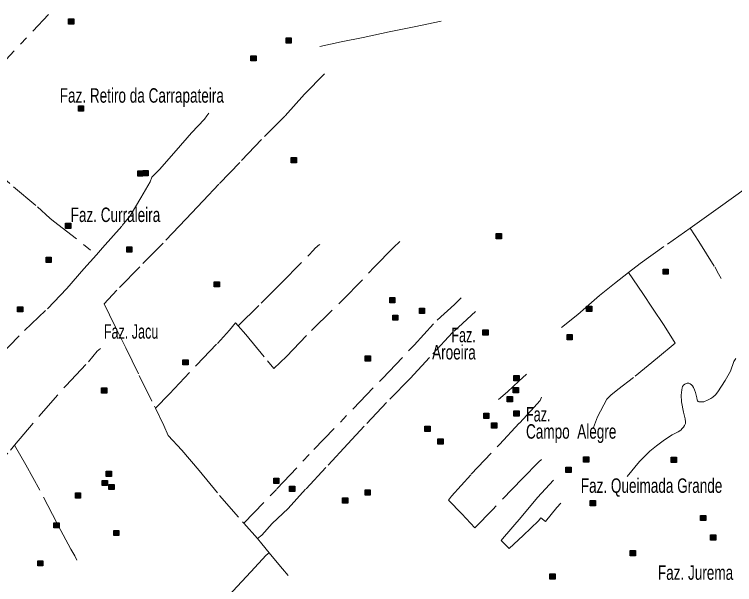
# Model space of a CAD drawing. Extents: x 445.6 to 500, y 8618.1 to 8673.4.
# Drawn here: x 465.21 to 473.17, y 8667.1 to 8673.41 of the extents above; entities that cross this region are included whole.
import ezdxf
from ezdxf.enums import TextEntityAlignment as Align

# ---------------------------------------------------------------- set-up
doc = ezdxf.new("R2010")
doc.units = 0
doc.header["$LTSCALE"] = 0.064
doc.linetypes.add('DOT_DASHED', pattern=[7.7, 5, -1.2, 0.3, -1.2])
doc.layers.add('2', color=7, linetype='Continuous', lineweight=25)
doc.layers.add('22', color=7, linetype='DOT_DASHED', lineweight=13)
doc.layers.add('61', color=7, linetype='Continuous')

msp = doc.modelspace()

# ---------------------------------------------------------------- hatches: boundary and pattern name
at = {"layer": '2'}
for points in [[(465.8078, 8673.3606), (465.8658, 8673.3606), (465.8658, 8673.3026), (465.8078, 8673.3026)], [(468.2112, 8673.1506), (468.2692, 8673.1506), (468.2692, 8673.0926), (468.2112, 8673.0926)], [(467.8227, 8672.9541), (467.8807, 8672.9541), (467.8807, 8672.8961), (467.8227, 8672.8961)], [(465.9159, 8672.3984), (465.9739, 8672.3984), (465.9739, 8672.3404), (465.9159, 8672.3404)], [(468.2684, 8671.8287), (468.3264, 8671.8287), (468.3264, 8671.7707), (468.2684, 8671.7707)], [(466.5717, 8671.6798), (466.6297, 8671.6798), (466.6297, 8671.6218), (466.5717, 8671.6218)], [(466.6291, 8671.6832), (466.6871, 8671.6832), (466.6871, 8671.6252), (466.6291, 8671.6252)], [(465.7746, 8671.1004), (465.8326, 8671.1004), (465.8326, 8671.0424), (465.7746, 8671.0424)], [(470.5333, 8670.9885), (470.5913, 8670.9885), (470.5913, 8670.9305), (470.5333, 8670.9305)], [(466.4499, 8670.841), (466.5079, 8670.841), (466.5079, 8670.783), (466.4499, 8670.783)], [(465.5581, 8670.7258), (465.6161, 8670.7258), (465.6161, 8670.6678), (465.5581, 8670.6678)], [(472.3785, 8670.5952), (472.4365, 8670.5952), (472.4365, 8670.5372), (472.3785, 8670.5372)], [(467.4159, 8670.4548), (467.4739, 8670.4548), (467.4739, 8670.3968), (467.4159, 8670.3968)], [(469.3571, 8670.2791), (469.4151, 8670.2791), (469.4151, 8670.2211), (469.3571, 8670.2211)], [(465.2441, 8670.178), (465.3021, 8670.178), (465.3021, 8670.12), (465.2441, 8670.12)], [(469.6848, 8670.1605), (469.7428, 8670.1605), (469.7428, 8670.1025), (469.6848, 8670.1025)], [(471.5339, 8670.1847), (471.5919, 8670.1847), (471.5919, 8670.1267), (471.5339, 8670.1267)], [(469.3909, 8670.0859), (469.4489, 8670.0859), (469.4489, 8670.0279), (469.3909, 8670.0279)], [(470.3868, 8669.9209), (470.4448, 8669.9209), (470.4448, 8669.8629), (470.3868, 8669.8629)], [(471.3177, 8669.8699), (471.3757, 8669.8699), (471.3757, 8669.8119), (471.3177, 8669.8119)], [(467.0698, 8669.5923), (467.1278, 8669.5923), (467.1278, 8669.5343), (467.0698, 8669.5343)], [(469.0869, 8669.6353), (469.1449, 8669.6353), (469.1449, 8669.5773), (469.0869, 8669.5773)], [(470.73, 8669.4159), (470.788, 8669.4159), (470.788, 8669.3579), (470.73, 8669.3579)], [(466.1713, 8669.2806), (466.2293, 8669.2806), (466.2293, 8669.2226), (466.1713, 8669.2226)], [(470.7232, 8669.2838), (470.7812, 8669.2838), (470.7812, 8669.2258), (470.7232, 8669.2258)], [(470.6564, 8669.1837), (470.7144, 8669.1837), (470.7144, 8669.1257), (470.6564, 8669.1257)], [(470.3963, 8669.0007), (470.4543, 8669.0007), (470.4543, 8668.9427), (470.3963, 8668.9427)], [(470.73, 8669.0263), (470.788, 8669.0263), (470.788, 8668.9683), (470.73, 8668.9683)], [(470.4841, 8668.8923), (470.5421, 8668.8923), (470.5421, 8668.8343), (470.4841, 8668.8343)], [(469.745, 8668.8576), (469.803, 8668.8576), (469.803, 8668.7996), (469.745, 8668.7996)], [(469.8896, 8668.7161), (469.9476, 8668.7161), (469.9476, 8668.6581), (469.8896, 8668.6581)], [(471.5001, 8668.5181), (471.5581, 8668.5181), (471.5581, 8668.4601), (471.5001, 8668.4601)], [(472.4696, 8668.5147), (472.5276, 8668.5147), (472.5276, 8668.4567), (472.4696, 8668.4567)], [(471.3042, 8668.4026), (471.3622, 8668.4026), (471.3622, 8668.3446), (471.3042, 8668.3446)], [(466.2236, 8668.3591), (466.2816, 8668.3591), (466.2816, 8668.3011), (466.2236, 8668.3011)], [(466.1797, 8668.2575), (466.2377, 8668.2575), (466.2377, 8668.1995), (466.1797, 8668.1995)], [(468.0745, 8668.2811), (468.1325, 8668.2811), (468.1325, 8668.2231), (468.0745, 8668.2231)], [(466.254, 8668.2134), (466.312, 8668.2134), (466.312, 8668.1554), (466.254, 8668.1554)], [(468.2491, 8668.1922), (468.3071, 8668.1922), (468.3071, 8668.1342), (468.2491, 8668.1342)], [(465.8823, 8668.1195), (465.9403, 8668.1195), (465.9403, 8668.0615), (465.8823, 8668.0615)], [(469.0845, 8668.1524), (469.1425, 8668.1524), (469.1425, 8668.0944), (469.0845, 8668.0944)], [(468.8355, 8668.0636), (468.8935, 8668.0636), (468.8935, 8668.0056), (468.8355, 8668.0056)], [(471.5727, 8668.0332), (471.6307, 8668.0332), (471.6307, 8667.9752), (471.5727, 8667.9752)], [(472.7935, 8667.8705), (472.8515, 8667.8705), (472.8515, 8667.8125), (472.7935, 8667.8125)], [(465.6439, 8667.7891), (465.7019, 8667.7891), (465.7019, 8667.7311), (465.6439, 8667.7311)], [(466.3059, 8667.7044), (466.3639, 8667.7044), (466.3639, 8667.6464), (466.3059, 8667.6464)], [(472.9049, 8667.6537), (472.9629, 8667.6537), (472.9629, 8667.5957), (472.9049, 8667.5957)], [(472.0152, 8667.4809), (472.0732, 8667.4809), (472.0732, 8667.4229), (472.0152, 8667.4229)], [(465.4658, 8667.369), (465.5238, 8667.369), (465.5238, 8667.311), (465.4658, 8667.311)], [(471.1269, 8667.2234), (471.1849, 8667.2234), (471.1849, 8667.1654), (471.1269, 8667.1654)]]:
    msp.add_hatch(color=256, dxfattribs=at).paths.add_polyline_path(points)

# ---------------------------------------------------------------- linework, layer by layer
for points in [[(465.8078, 8673.3606), (465.8658, 8673.3606), (465.8658, 8673.3026), (465.8078, 8673.3026)], [(468.2112, 8673.1506), (468.2692, 8673.1506), (468.2692, 8673.0926), (468.2112, 8673.0926)], [(467.8227, 8672.9541), (467.8807, 8672.9541), (467.8807, 8672.8961), (467.8227, 8672.8961)], [(465.9159, 8672.3984), (465.9739, 8672.3984), (465.9739, 8672.3404), (465.9159, 8672.3404)], [(468.2684, 8671.8287), (468.3264, 8671.8287), (468.3264, 8671.7707), (468.2684, 8671.7707)], [(466.5717, 8671.6798), (466.6297, 8671.6798), (466.6297, 8671.6218), (466.5717, 8671.6218)], [(466.6291, 8671.6832), (466.6871, 8671.6832), (466.6871, 8671.6252), (466.6291, 8671.6252)], [(465.7746, 8671.1004), (465.8326, 8671.1004), (465.8326, 8671.0424), (465.7746, 8671.0424)], [(470.5333, 8670.9885), (470.5913, 8670.9885), (470.5913, 8670.9305), (470.5333, 8670.9305)], [(466.4499, 8670.841), (466.5079, 8670.841), (466.5079, 8670.783), (466.4499, 8670.783)], [(465.5581, 8670.7258), (465.6161, 8670.7258), (465.6161, 8670.6678), (465.5581, 8670.6678)], [(472.3785, 8670.5952), (472.4365, 8670.5952), (472.4365, 8670.5372), (472.3785, 8670.5372)], [(467.4159, 8670.4548), (467.4739, 8670.4548), (467.4739, 8670.3968), (467.4159, 8670.3968)], [(469.3571, 8670.2791), (469.4151, 8670.2791), (469.4151, 8670.2211), (469.3571, 8670.2211)], [(465.2441, 8670.178), (465.3021, 8670.178), (465.3021, 8670.12), (465.2441, 8670.12)], [(469.6848, 8670.1605), (469.7428, 8670.1605), (469.7428, 8670.1025), (469.6848, 8670.1025)], [(471.5339, 8670.1847), (471.5919, 8670.1847), (471.5919, 8670.1267), (471.5339, 8670.1267)], [(469.3909, 8670.0859), (469.4489, 8670.0859), (469.4489, 8670.0279), (469.3909, 8670.0279)], [(470.3868, 8669.9209), (470.4448, 8669.9209), (470.4448, 8669.8629), (470.3868, 8669.8629)], [(471.3177, 8669.8699), (471.3757, 8669.8699), (471.3757, 8669.8119), (471.3177, 8669.8119)], [(467.0698, 8669.5923), (467.1278, 8669.5923), (467.1278, 8669.5343), (467.0698, 8669.5343)], [(469.0869, 8669.6353), (469.1449, 8669.6353), (469.1449, 8669.5773), (469.0869, 8669.5773)], [(470.73, 8669.4159), (470.788, 8669.4159), (470.788, 8669.3579), (470.73, 8669.3579)], [(466.1713, 8669.2806), (466.2293, 8669.2806), (466.2293, 8669.2226), (466.1713, 8669.2226)], [(470.7232, 8669.2838), (470.7812, 8669.2838), (470.7812, 8669.2258), (470.7232, 8669.2258)], [(470.6564, 8669.1837), (470.7144, 8669.1837), (470.7144, 8669.1257), (470.6564, 8669.1257)], [(470.3963, 8669.0007), (470.4543, 8669.0007), (470.4543, 8668.9427), (470.3963, 8668.9427)], [(470.73, 8669.0263), (470.788, 8669.0263), (470.788, 8668.9683), (470.73, 8668.9683)], [(470.4841, 8668.8923), (470.5421, 8668.8923), (470.5421, 8668.8343), (470.4841, 8668.8343)], [(469.745, 8668.8576), (469.803, 8668.8576), (469.803, 8668.7996), (469.745, 8668.7996)], [(469.8896, 8668.7161), (469.9476, 8668.7161), (469.9476, 8668.6581), (469.8896, 8668.6581)], [(471.5001, 8668.5181), (471.5581, 8668.5181), (471.5581, 8668.4601), (471.5001, 8668.4601)], [(472.4696, 8668.5147), (472.5276, 8668.5147), (472.5276, 8668.4567), (472.4696, 8668.4567)], [(471.3042, 8668.4026), (471.3622, 8668.4026), (471.3622, 8668.3446), (471.3042, 8668.3446)], [(466.2236, 8668.3591), (466.2816, 8668.3591), (466.2816, 8668.3011), (466.2236, 8668.3011)], [(466.1797, 8668.2575), (466.2377, 8668.2575), (466.2377, 8668.1995), (466.1797, 8668.1995)], [(468.0745, 8668.2811), (468.1325, 8668.2811), (468.1325, 8668.2231), (468.0745, 8668.2231)], [(466.254, 8668.2134), (466.312, 8668.2134), (466.312, 8668.1554), (466.254, 8668.1554)], [(468.2491, 8668.1922), (468.3071, 8668.1922), (468.3071, 8668.1342), (468.2491, 8668.1342)], [(465.8823, 8668.1195), (465.9403, 8668.1195), (465.9403, 8668.0615), (465.8823, 8668.0615)], [(469.0845, 8668.1524), (469.1425, 8668.1524), (469.1425, 8668.0944), (469.0845, 8668.0944)], [(468.8355, 8668.0636), (468.8935, 8668.0636), (468.8935, 8668.0056), (468.8355, 8668.0056)], [(471.5727, 8668.0332), (471.6307, 8668.0332), (471.6307, 8667.9752), (471.5727, 8667.9752)], [(472.7935, 8667.8705), (472.8515, 8667.8705), (472.8515, 8667.8125), (472.7935, 8667.8125)], [(465.6439, 8667.7891), (465.7019, 8667.7891), (465.7019, 8667.7311), (465.6439, 8667.7311)], [(466.3059, 8667.7044), (466.3639, 8667.7044), (466.3639, 8667.6464), (466.3059, 8667.6464)], [(472.9049, 8667.6537), (472.9629, 8667.6537), (472.9629, 8667.5957), (472.9049, 8667.5957)], [(472.0152, 8667.4809), (472.0732, 8667.4809), (472.0732, 8667.4229), (472.0152, 8667.4229)], [(465.4658, 8667.369), (465.5238, 8667.369), (465.5238, 8667.311), (465.4658, 8667.311)], [(471.1269, 8667.2234), (471.1849, 8667.2234), (471.1849, 8667.1654), (471.1269, 8667.1654)]]:
    msp.add_lwpolyline(points, close=True, dxfattribs=at)
at = {"layer": '22'}
msp.add_line((467.7443, 8667.783), (467.8943, 8667.6129), dxfattribs=at)
for points in [[(464.3711, 8672.1461), (464.6308, 8672.409), (464.7799, 8672.563), (464.9881, 8672.7735), (465.5838, 8673.4113)], [(468.5865, 8673.0576), (468.8219, 8673.1076), (469.0624, 8673.1551), (469.3529, 8673.2176), (469.6259, 8673.2751), (469.9265, 8673.3352)], [(468.6369, 8672.7549), (468.4154, 8672.5273), (468.1972, 8672.2869), (467.9404, 8672.0273), (467.6988, 8671.7725), (467.4676, 8671.5321), (467.2943, 8671.3494), (467.1038, 8671.1455), (466.8534, 8670.8826), (466.5934, 8670.6198), (466.339, 8670.3616), (466.199, 8670.2116), (466.2599, 8670.09), (466.3261, 8669.9525), (466.4404, 8669.7233), (466.5887, 8669.4192), (466.7561, 8669.0764), (466.7665, 8669.0557)], [(466.1156, 8670.7528), (466.1838, 8670.8294), (466.3993, 8671.0763), (466.4868, 8671.1826), (466.605, 8671.3809), (466.7096, 8671.5596), (466.7285, 8671.6116), (466.8113, 8671.6966), (466.9957, 8671.9044), (467.1666, 8672.1019), (467.3085, 8672.2507), (467.3369, 8672.2908), (467.3582, 8672.3182)], [(464.6641, 8671.9591), (464.7135, 8671.9252), (464.9165, 8671.7481), (465.1999, 8671.5055), (465.4621, 8671.2822), (465.6009, 8671.159), (465.642, 8671.1256), (466.1156, 8670.7528)], [(472.6777, 8671.0481), (472.8083, 8671.1401), (473.0137, 8671.2875), (473.2868, 8671.4823), (473.499, 8671.6321), (473.536, 8671.6551), (473.6421, 8671.3879), (473.7205, 8671.1667), (473.795, 8670.9812), (473.8365, 8670.8545), (473.8438, 8670.8006)], [(471.9968, 8670.5555), (472.127, 8670.6573), (472.4269, 8670.8715), (472.6777, 8671.0481)], [(472.6777, 8671.0481), (472.7754, 8670.8979), (472.9501, 8670.6198), (472.9911, 8670.5435), (473.0203, 8670.4886)], [(467.6821, 8669.9657), (467.765, 8669.8714), (468.005, 8669.5813), (468.0776, 8669.493), (468.2165, 8669.6286), (468.4944, 8669.9155), (468.8323, 8670.2466), (469.1873, 8670.6139), (469.3988, 8670.8314), (469.4683, 8670.8977)], [(467.6821, 8669.9657), (467.9354, 8670.2182), (468.1564, 8670.4389), (468.5237, 8670.8132), (468.5648, 8670.8542), (468.585, 8670.8655)], [(464.0555, 8668.3656), (464.0932, 8668.453), (464.1736, 8668.5805), (464.2847, 8668.7387), (464.3557, 8668.8473), (464.4861, 8669.0399), (464.5098, 8669.0895), (464.654, 8669.2265), (464.803, 8669.387), (465.0378, 8669.6271), (465.3216, 8669.9152), (465.573, 8670.155), (465.7882, 8670.3793), (465.9757, 8670.5956), (466.1156, 8670.7528)], [(471.2559, 8669.95), (471.4364, 8670.0938), (471.6764, 8670.3012), (471.8425, 8670.4348), (471.9968, 8670.5555)], [(471.9968, 8670.5555), (472.1554, 8670.3249), (472.2637, 8670.1627), (472.39, 8669.969), (472.5141, 8669.7741), (472.3179, 8669.6119), (472.0512, 8669.3943), (471.8775, 8669.2614), (471.8025, 8669.1996), (471.7574, 8669.1568), (471.6559, 8668.9586), (471.6085, 8668.8414)], [(467.7443, 8667.783), (468.1113, 8668.1635), (468.5196, 8668.5996), (468.9537, 8669.0484), (469.2768, 8669.3852), (469.626, 8669.7525), (469.8816, 8670.0291), (470.0741, 8670.2043), (470.1487, 8670.2752)], [(470.3049, 8670.1263), (470.0528, 8669.8923), (469.7971, 8669.6157), (469.5828, 8669.3859), (469.3236, 8669.12), (469.075, 8668.8577), (468.8939, 8668.6627), (468.6516, 8668.3983), (468.4279, 8668.1607), (468.2354, 8667.9464), (468.0579, 8667.7798), (467.9443, 8667.6522), (467.8943, 8667.6129)], [(466.7665, 8669.0557), (466.9237, 8669.2157), (467.2215, 8669.5326), (467.452, 8669.7723), (467.5846, 8669.9173), (467.6513, 8670.0007), (467.6821, 8669.9657)], [(465.2099, 8668.646), (465.4791, 8668.9637), (465.7789, 8669.3065), (466.0277, 8669.5689), (466.1233, 8669.6861), (466.1619, 8669.7164)], [(471.9816, 8668.2992), (472.1193, 8668.4675), (472.2344, 8668.5804), (472.3084, 8668.6399), (472.3968, 8668.7076), (472.481, 8668.761), (472.5473, 8668.7949), (472.5741, 8668.8134), (472.5905, 8668.8319), (472.6049, 8668.8462), (472.6172, 8668.8647), (472.6254, 8668.8852), (472.6254, 8668.9057), (472.6234, 8668.9365), (472.6049, 8669.0124), (472.5823, 8669.1274), (472.5782, 8669.1982), (472.5864, 8669.2598), (472.5905, 8669.2803), (472.5946, 8669.2947), (472.6049, 8669.309), (472.6193, 8669.3213), (472.646, 8669.3316), (472.6645, 8669.3316), (472.6789, 8669.3234), (472.6933, 8669.3131), (472.7056, 8669.3029), (472.7138, 8669.2864), (472.7262, 8669.2598), (472.7385, 8669.229), (472.7447, 8669.1982), (472.7508, 8669.1695), (472.7549, 8669.1469), (472.7591, 8669.1366), (472.7673, 8669.1284), (472.7755, 8669.1243), (472.7919, 8669.1243), (472.8043, 8669.1243), (472.831, 8669.1264), (472.8762, 8669.1469), (472.907, 8669.1613), (472.9296, 8669.1777), (472.9584, 8669.2044), (472.9831, 8669.2372), (473.0242, 8669.3008), (473.0673, 8669.3603), (473.1228, 8669.467), (473.1624, 8669.5707), (473.185, 8669.6056)], [(470.5612, 8669.1506), (470.6592, 8669.2381), (470.7842, 8669.3531), (470.8697, 8669.4319)], [(471.0352, 8668.4897), (471.0048, 8668.464), (470.8266, 8668.2787), (470.4964, 8667.9351), (470.2983, 8667.7338), (470.1558, 8667.8865), (470.0064, 8668.0392), (470.0387, 8668.0824), (470.2576, 8668.3253), (470.5704, 8668.655), (470.7905, 8668.8919), (470.9158, 8669.0278), (471.021, 8669.1395), (471.0342, 8669.179)], [(466.7665, 8669.0557), (466.862, 8668.8648), (466.9099, 8668.7546), (467.0583, 8668.5906), (467.2516, 8668.3658), (467.4767, 8668.0908), (467.7288, 8667.8006), (467.7443, 8667.783)], [(464.9215, 8668.3221), (465.1649, 8668.5928), (465.2099, 8668.646)], [(465.2099, 8668.646), (465.3357, 8668.4283), (465.5312, 8668.0725), (465.692, 8667.7601), (465.8318, 8667.4976), (465.8752, 8667.4238), (465.8987, 8667.3753)], [(471.1663, 8668.2597), (470.992, 8668.0688), (470.8099, 8667.852), (470.605, 8667.6113), (470.589, 8667.5922), (470.6784, 8667.5029), (470.8317, 8667.6464), (471.001, 8667.8091), (471.0297, 8667.8441), (471.0808, 8667.8027), (471.2053, 8667.9557), (471.248, 8668.0066)], [(467.8943, 8667.6129), (467.9433, 8667.5573), (468.0233, 8667.457)], [(465.8829, 8665.178), (466.1402, 8665.4275), (466.409, 8665.7115), (466.7695, 8666.1099), (467.0633, 8666.4345), (467.1478, 8666.5251), (467.4455, 8666.8452), (467.6237, 8667.0326), (467.8213, 8667.2463), (467.9901, 8667.4305), (468.0233, 8667.457)], [(468.0233, 8667.457), (468.0572, 8667.4145), (468.1719, 8667.2781), (468.2355, 8667.204)]]:
    msp.add_lwpolyline(points, dxfattribs=at)

# ---------------------------------------------------------------- texts
at = {"layer": '61'}
for s, width, p in [('Faz. Retiro da Carrapateira', 0.7, (465.7095, 8672.4347)), ('Faz. Curraleira', 0.7, (465.8302, 8671.1151)), ('Faz.', 0.65, (470.8642, 8668.9086)), ('Campo  Alegre', 0.7, (470.8642, 8668.7186)), ('Faz. Queimada Grande', 0.7, (471.4695, 8668.1196)), ('Faz. Jurema', 0.7, (472.3221, 8667.1576))]:
    msp.add_text(s, height=0.16, dxfattribs=dict(at, width=width)).set_placement(p)
at = {"layer": '61', "width": 0.65}
msp.add_text('Faz. Jacu', height=0.16, dxfattribs=at).set_placement((466.4984, 8669.8245), align=Align.CENTER)
at = {"layer": '61'}
for s, width, p in [('Faz.', 0.65, (470.3088, 8669.7849)), ('Aroeira', 0.7, (470.3088, 8669.5949))]:
    msp.add_text(s, height=0.16, dxfattribs=dict(at, width=width)).set_placement(p, align=Align.RIGHT)

doc.saveas('drawing.dxf')
